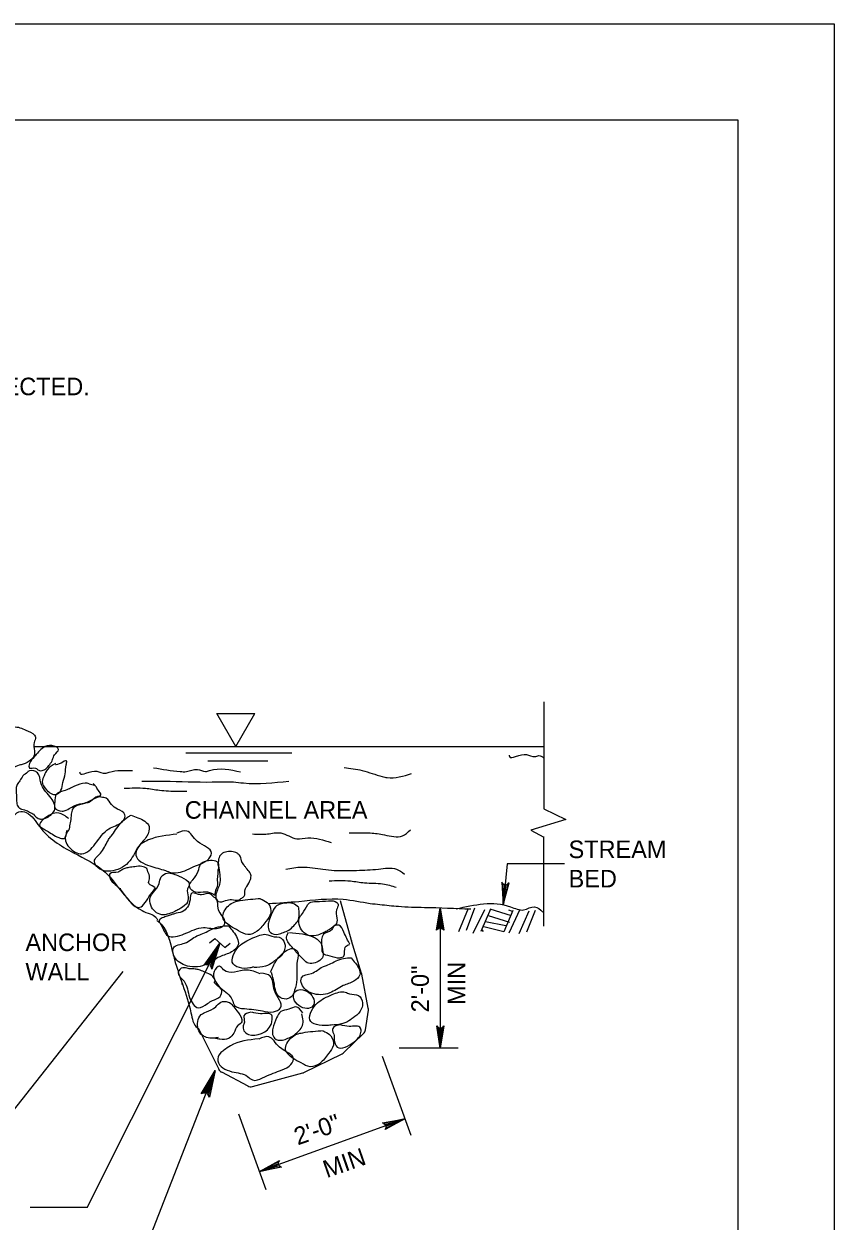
# Model space of a CAD drawing. Extents: x 5 to 910, y -47 to 547.
# Drawn here: x 719.1 to 845.7, y 360.5 to 547.5 of the extents above; entities that cross this region are included whole.
import ezdxf

# ---------------------------------------------------------------- set-up
doc = ezdxf.new("R2010")
doc.units = 0
for name, color, linetype in [('1', 7, 'Continuous'), ('2', 7, 'Continuous'), ('3', 7, 'Continuous'), ('PLT-BNDY', 7, 'Continuous')]:
    doc.layers.add(name, color=color, linetype=linetype)

msp = doc.modelspace()

# ---------------------------------------------------------------- linework, layer by layer
at = {"layer": '1'}
for p, q in [((789.55, 409.4), (788.23, 405.9)), ((788.54, 409.36), (787.03, 405.68)), ((791.09, 409.11), (789.25, 405.42)), ((792.05, 409.22), (790.54, 405.77)), ((795.04, 407.14), (791.72, 408.21)), ((795.32, 408.21), (792, 409.24)), ((795.51, 409.02), (794.11, 405.7)), ((796.61, 409.2), (794.91, 405.51)), ((795.46, 408.88), (794.91, 409.06)), ((798.01, 408.9), (796.47, 405.4)), ((799.03, 409.04), (797.65, 405.63)), ((790.95, 405.74), (790.73, 406)), ((794.11, 405.7), (790.76, 406.52)), ((794.44, 406.66), (791.25, 407.28))]:
    msp.add_line(p, q, dxfattribs=at)
msp.add_lwpolyline([(830.72, -31.53), (830.72, 532.47), (44.72, 532.47), (44.72, -31.53), (830.72, -31.53), (830.72, -5.17), (630.72, -5.17), (630.72, 59.51), (830.72, 59.51), (830.72, 88.47), (630.72, 88.47), (630.72, -31.53), (709.52, -31.53), (709.52, -5.17), (709.52, -31.53), (786.52, -31.53), (786.52, -5.17), (786.52, -17.48), (830.72, -17.48)], dxfattribs=at)
at = {"layer": '2'}
for p, q in [((800.34, 441.62), (800.34, 424.89)), ((749.26, 439.81), (755.19, 439.81)), ((752.21, 434.66), (749.26, 439.81)), ((752.21, 434.66), (755.19, 439.81)), ((720.8, 434.66), (800.34, 434.66)), ((744.39, 433.63), (760.98, 433.63)), ((747.84, 432.4), (757.22, 432.4)), ((800.32, 420.61), (800.3, 406.59)), ((794.65, 416.34), (794.03, 409.91)), ((803.59, 416.34), (794.65, 416.34)), ((784.17, 409.44), (784.17, 387.58)), ((734.57, 399.52), (716.43, 376.57)), ((786.98, 387.51), (777.76, 387.51)), ((775.1, 386.28), (779.59, 373.94)), ((752.65, 377.26), (756.93, 365.46)), ((778.66, 376.52), (755.92, 368.27)), ((729.02, 362.65), (720.07, 362.65))]:
    msp.add_line(p, q, dxfattribs=at)
for points in [[(800.34, 424.89), (803.82, 423.25), (798.33, 421.55), (800.34, 420.48)], [(793.94, 413.25), (794.17, 413.11), (794.03, 409.91), (793.94, 413.25), (793.8, 413.43), (794.03, 409.91), (794.49, 413.06), (794.74, 413.18), (794.03, 409.91), (794.92, 413.34), (794.74, 413.18)], [(783.76, 406.12), (783.99, 406.23), (784.17, 409.44), (783.76, 406.12), (783.6, 405.94), (784.17, 409.44), (784.33, 406.23), (784.56, 406.12), (784.17, 409.44), (784.72, 405.94), (784.56, 406.12)], [(747.53, 400.58), (747.85, 400.56), (749.74, 403.93), (747.53, 400.58), (747.28, 400.47), (749.74, 403.93), (748.22, 400.39), (748.42, 400.15), (749.74, 403.93), (748.48, 399.87), (748.42, 400.15)], [(784.58, 390.83), (784.35, 390.71), (784.17, 387.51), (784.58, 390.83), (784.74, 391.01), (784.17, 387.51), (784.01, 390.71), (783.78, 390.83), (784.17, 387.51), (783.62, 391.01), (783.78, 390.83)], [(747.07, 380.51), (747.39, 380.55), (748.98, 384.03), (747.07, 380.51), (746.82, 380.38), (748.98, 384.03), (747.76, 380.39), (747.98, 380.14), (748.98, 384.03), (748.09, 379.88), (747.98, 380.14)], [(775.38, 375.78), (775.59, 375.6), (778.66, 376.52), (775.38, 375.78), (775.16, 375.88), (778.66, 376.52), (775.68, 375.28), (775.66, 375.05), (778.66, 376.52), (775.57, 374.82), (775.66, 375.05)], [(759.19, 369), (759.01, 369.18), (755.92, 368.27), (759.19, 369), (759.39, 368.93), (755.92, 368.27), (758.89, 369.5), (758.91, 369.78), (755.92, 368.27), (759.03, 369.98), (758.91, 369.78)]]:
    msp.add_lwpolyline(points, dxfattribs=at)
for points in [[(794.97, 433.31), (794.99, 433.06), (795.95, 433.06), (797.67, 433.38), (798.95, 433.06), (799.59, 433.22), (800.32, 432.88)], [(727.82, 430.7), (727.85, 430.45), (728.81, 430.45), (730.52, 430.77), (731.81, 430.45), (732.45, 430.61), (736.06, 430.87)], [(739.36, 431.33), (743.54, 430.73), (744.5, 430.73), (746.22, 431.06), (747.5, 430.73), (748.14, 430.89), (752.98, 430.67)], [(769.14, 431.37), (771.98, 430.89), (775.11, 429.95), (775.89, 429.79), (779.67, 430.41)], [(734.8, 428.12), (738.09, 428.12), (740.29, 427.82), (743.13, 427.66), (744.55, 427.64)], [(737.55, 429.24), (741, 429.24), (748.55, 429.1), (751.85, 429.1), (753.43, 428.94), (760.5, 429.24)], [(754.84, 420.98), (757.2, 420.98), (759.26, 421.14), (761.75, 420.23), (763.49, 420.36), (767.13, 419.63)], [(769.94, 421.14), (773.24, 421.14), (775.44, 420.84), (778.27, 420.68), (779.53, 421.62)], [(760.04, 415.49), (762.55, 415.81), (765.85, 415.49), (767.62, 415.3), (771.11, 415.3), (774.5, 415.49), (777.33, 415.49), (778.59, 414.71)], [(766.84, 413.65), (770.14, 413.65), (772.33, 413.35), (775.17, 413.19), (777.31, 412.65)], [(762.04, 409.55), (761.16, 410.11), (759.84, 410.15), (758.61, 409.78), (757.95, 408.78), (757.33, 407.11), (757.28, 406.44), (757.63, 405.6), (758.84, 405.32), (759.68, 405.6), (760.51, 405.98), (761.29, 406.65), (761.9, 407.38), (762.05, 409.52)], [(757.36, 410.11), (762.07, 410.46), (769.01, 410.78), (773.24, 410.14), (776.21, 409.82), (777.63, 409.68), (781.7, 409.52), (788.93, 409.28)], [(786.68, 409.28), (795.15, 409.61), (797.21, 409.13), (798.91, 409.61), (800.21, 408.79)], [(757.63, 399.39), (758.54, 401.18), (760.14, 402.78), (761.15, 403.07), (761.81, 402.73), (761.81, 401.13), (761.77, 398.27), (761.42, 396.6), (761.08, 395.78), (760.1, 395.2), (758.91, 395.66), (758.2, 397.81), (757.81, 399.34)], [(754.55, 393.14), (753.49, 392.59), (753.56, 391.58), (753.38, 391.03), (753.49, 390.25), (754.2, 389.68), (757.73, 391.21), (757.89, 391.97), (757.84, 392.66), (756.07, 392.91), (754.73, 393.14)], [(762.7, 393.03), (761.6, 393.96), (760.5, 393.62), (759.27, 393.25), (758.61, 392.25), (757.99, 390.58), (757.94, 389.91), (758.29, 389.07), (759.5, 388.79), (760.34, 389.07), (761.17, 389.46), (761.95, 390.12), (762.56, 390.85), (762.56, 392.91)], [(768.66, 391.16), (767.38, 390.6), (767.37, 390.12), (767.54, 389.71), (767.61, 388.85), (768.09, 387.7), (770.71, 388.53), (771.77, 389.99), (771.72, 390.67), (769.96, 390.93), (768.61, 391.15)]]:
    msp.add_spline(points, degree=3, dxfattribs=at)
at = {"layer": '3'}
for p, q in [((729.33, 428.83), (730.16, 428.62)), ((734.14, 412.54), (734.12, 412.38)), ((770.32, 404.33), (768.6, 410.53)), ((729.02, 362.65), (749.74, 403.93)), ((771.89, 399.21), (770.33, 404.31)), ((772.93, 393.77), (771.92, 399.11)), ((743.84, 397.62), (743.73, 397.46)), ((772.49, 390.38), (772.94, 393.44)), ((746.38, 390.6), (749.55, 384.24)), ((769.11, 386.84), (772.19, 389.8)), ((762.87, 383.73), (768.86, 386.66)), ((735.14, 348.64), (748.69, 383.3)), ((749.98, 383.81), (754.11, 381.63)), ((754.83, 381.55), (762.69, 383.67))]:
    msp.add_line(p, q, dxfattribs=at)
msp.add_lwpolyline([(748.12, 403.98), (748.93, 404.64), (750.53, 403.25), (751.32, 403.95)], dxfattribs=at)
for centre, start, end in [((771.28, 404.6), 195.4612, 197.1027), ((770.94, 398.92), 10.7843, 17.1027), ((771.95, 393.59), 351.573, 10.7843), ((771.5, 390.52), 313.8767, 351.573), ((768.42, 387.56), 296.0754, 313.8767), ((750.44, 384.69), 206.5229, 242.1759), ((762.43, 384.63), 285.1011, 296.0754), ((754.57, 382.51), 242.1759, 285.1011)]:
    msp.add_arc(centre, 1, start, end, dxfattribs=at)
msp.add_ellipse((762.85, 395.2), major_axis=(-1.43, 1.06), ratio=0.71898, dxfattribs=at)
for points in [[(693.23, 441.25), (696, 438.96), (698.93, 437.45), (700.46, 437.32), (703.39, 434.02), (703.92, 432.74), (703, 430.82), (701.13, 426.08), (700.97, 424.69), (701.74, 423.54), (704.92, 421.64), (710.67, 417.8), (714.12, 418.3), (716.29, 421.64), (717.19, 423.29), (718.33, 424.44), (719.47, 424.32), (721.53, 422.15), (726.86, 418.05), (731.83, 414.99), (734.51, 411.81), (737.57, 409.02), (738.83, 408.49), (739.72, 407.99), (740, 407.55)], [(718.76, 431.78), (718.6, 431.76), (716.66, 431.21), (714.94, 432.65), (714.88, 433.86), (715.36, 434.69), (716.25, 436.08), (716.59, 437.11), (717.55, 437.68), (719.41, 437.2), (720.78, 436.4), (720.94, 436.08), (720.71, 435.26), (720.78, 433.95), (720.55, 432.92), (720.46, 432.81), (719.31, 432.01), (718.65, 431.78)], [(722.56, 431.14), (723.59, 432.6), (723.91, 433.34), (724.53, 434.18), (723.48, 434.8), (722.15, 434.48), (720.71, 433.01), (719.98, 431.99), (719.98, 431.28), (720.92, 431.28), (721.42, 430.93), (722.58, 431.14)], [(724.05, 431.96), (722.78, 431.07), (722.27, 430.08), (721.98, 429.17), (722.65, 427.89), (724.14, 427.16), (724.9, 427.8), (725.19, 429.01), (725.56, 430.38), (725.72, 431.78), (725.81, 432.35), (724.14, 431.78), (724.05, 431.78)], [(720.62, 424.05), (721.35, 423.41), (721.85, 423.31), (722.72, 423.54), (723.94, 424.87), (723.18, 426.81), (721.76, 428.94), (721.21, 430.54), (720.96, 430.71), (719.75, 430.71), (719.68, 430.64), (718.95, 430.04), (718.46, 429.27), (718.05, 428.72), (717.9, 428.06), (717.9, 427.59), (717.94, 427.11), (717.99, 425.85), (718.24, 425.17), (718.76, 424.87), (719.66, 424.57), (720, 424.39), (720.71, 424.07)], [(729.33, 428.83), (728.67, 428.92), (727.02, 428.44), (725.35, 427.71), (724.16, 427.16), (723.94, 426.01), (723.94, 425.08), (725.08, 424.55), (725.72, 424.71), (727.55, 425.6), (728.81, 425.88), (730.5, 426.7), (731.12, 427.07), (730.75, 427.78), (730.32, 428.46), (729.95, 428.85)], [(726.09, 421.6), (725.58, 420.52), (725.63, 419.91), (726.18, 418.92), (728.17, 417.87), (730.25, 419.43), (732.4, 421.78), (734.44, 422.86), (734.89, 423.57), (734.89, 423.98), (733.75, 424.87), (732.81, 425.56), (731.99, 426.56), (731.21, 426.72), (730.62, 426.84), (729.52, 426.04), (728.95, 425.83), (727.44, 425.4), (726.73, 424.87), (726.52, 424.09), (726.38, 422.97), (726.29, 422.49), (726.15, 421.55)], [(726.11, 423.38), (724.55, 424.23), (722.08, 423.18), (721.56, 422.38), (722.61, 421.53), (724.55, 420.41), (725.4, 420.29), (725.81, 421.53)], [(735.86, 423.91), (736.93, 423.52), (738.67, 422.15), (738.33, 420.66), (737.07, 419.1), (735.67, 416.79), (733, 415.24), (730.71, 415.67), (730.14, 416.66), (731.23, 418.17), (732.35, 420.11), (732.77, 420.66), (733.45, 421.6), (734.3, 422.72), (735.31, 423.61), (735.88, 423.93)], [(742.99, 420.94), (738.55, 420.04), (737.59, 419.52), (736.93, 418.83), (736.61, 417.69), (738.78, 415.99), (741.23, 415.26), (742.07, 414.98), (743.57, 415.01), (746.24, 416.13), (747.75, 416.86), (748.42, 417.96), (746.24, 419.81), (744.55, 421.44), (742.99, 421.1)], [(748.9, 411.41), (748.49, 411.68), (747.14, 411.88), (745.59, 412.01), (745.01, 412.97), (745.49, 413.8), (746.36, 415.17), (746.7, 416.22), (747.66, 416.79), (749.41, 416.37), (749.4, 416.21), (749.51, 415.91), (749.46, 415.5), (749.4, 414.72), (749.33, 413.69), (749.33, 412.85), (749.14, 412.39), (748.9, 411.38)], [(753.11, 416.77), (752.79, 417.69), (752.42, 417.98), (751.57, 418.24), (749.83, 417.69), (749.56, 415.67), (749.67, 413.09), (749.1, 411.33), (749.24, 410.69), (749.49, 410.46), (750.63, 410.57), (751.57, 410.75), (752.63, 410.66), (753.15, 410.98), (753.52, 411.26), (753.7, 412.33), (753.93, 412.79), (754.5, 413.87), (754.59, 414.6), (754.32, 415.1), (753.72, 415.83), (753.49, 416.18), (753.04, 416.75)], [(738.35, 415.58), (737.53, 415.92), (736.45, 415.86), (735.53, 415.74), (734.89, 415.58), (734.35, 415.31), (733.82, 415.03), (732.56, 414.78), (732.72, 413.77), (733.64, 412.86), (737.43, 409.59), (738.26, 410.53), (739.15, 411.85), (739.61, 412.58), (738.62, 413.23), (738.72, 413.96), (738.72, 414.41), (738.42, 415.31), (738.34, 415.59)], [(742.72, 408.89), (741.77, 408.51), (740.64, 408.37), (738.94, 409.84), (738.85, 411.07), (739.36, 411.88), (740.23, 413.25), (740.57, 414.28), (741.51, 414.87), (743.38, 414.37), (744.76, 413.57), (744.94, 413.25), (744.69, 412.42), (744.76, 411.14), (744.53, 410.09), (744.46, 410.02), (743.31, 409.2), (742.71, 408.89)], [(741.53, 408.16), (740.74, 407.86), (740.23, 407.44), (740.43, 406.98), (741.6, 405.08), (744.18, 405.38), (747.18, 406.36), (749.49, 406.25), (750.25, 406.61), (750.5, 407), (749.95, 408.4), (749.45, 409.4), (749.26, 410.69), (748.64, 411.26), (748.16, 411.65), (746.86, 411.49), (746.24, 411.6), (745.33, 411.75), (745.07, 410.71), (743.84, 408.84), (742.62, 408.52), (742.11, 408.34), (741.47, 408.14)], [(756.03, 410.85), (756.33, 410.73), (757.32, 410.07), (757.68, 408.6), (756.93, 407.32), (755.55, 405.79), (754.09, 405.26), (752.65, 405.86), (751.39, 406.57), (750.61, 407.23), (750.22, 407.94), (750.43, 408.9), (751.98, 410.34), (752.9, 410.57), (756.1, 410.91)], [(765.99, 405.58), (765.04, 405.2), (763.91, 405.07), (762.21, 406.53), (762.12, 407.77), (762.63, 408.57), (763.5, 409.94), (763.73, 410.21), (764.79, 410.44), (766.73, 410.53), (768.03, 410.26), (768.21, 409.94), (767.96, 409.12), (768.03, 407.84), (767.8, 406.78), (767.73, 406.72), (766.58, 405.89), (765.98, 405.58)], [(739.86, 407.46), (740.02, 407.35), (742.42, 402.2), (743.95, 397.35), (745.21, 393.07), (746.24, 390.69), (746.38, 390.6)], [(751.09, 406.61), (751.82, 405.72), (752.6, 403.68), (751.55, 402.56), (749.72, 401.81), (747.39, 400.53), (744.27, 400.48), (742.51, 402.06), (742.47, 403.18), (744.23, 403.94), (746.15, 405.06), (746.79, 405.31), (747.84, 405.79), (749.12, 406.36), (750.47, 406.61), (751.09, 406.64)], [(770.06, 403.75), (769.12, 405.64), (768.3, 406.74), (767.5, 406.51), (767.16, 405.95), (765.93, 405.32), (765.73, 404.91), (765.6, 404.13), (765.67, 403.01), (765.76, 402.46), (766.9, 401.96), (768.46, 401.64), (769.1, 401.92), (769.33, 403.31), (770.01, 403.72)], [(754.98, 400.24), (754.43, 400.06), (751.68, 400.97), (751.96, 402.35), (752.9, 403.6), (755.19, 404.88), (757.24, 405.25), (757.88, 405), (759.3, 404.72), (759.92, 403.6), (759.3, 401.96), (758.16, 401.04), (758.04, 400.95), (756.86, 400.35), (755.05, 400.13)], [(760.59, 405.58), (762.67, 405.37), (765.44, 404.02), (765.85, 402.56), (765.76, 401.64), (765.35, 401.23), (763.38, 400.88), (762.67, 401.53), (761.62, 402.56), (761.3, 402.97), (760.27, 404.34), (760.18, 405.05), (760.47, 405.58)], [(748.99, 398.19), (748.46, 398.88), (747.48, 399.36), (746.65, 399.7), (746.01, 399.86), (745.37, 399.91), (744.78, 399.96), (743.94, 400.09), (743.22, 399.41), (744.14, 397.97), (745, 395.46), (746.36, 393.85), (747.8, 394.51), (748.58, 394.95), (749.77, 395.61), (750.03, 396.55), (749.64, 397.07), (748.92, 397.9), (749.15, 398.06)], [(756.02, 399.12), (753.93, 399.72), (750.32, 399.78), (749.68, 400.33), (748.86, 399.51), (749.91, 396.92), (751.65, 395.09), (752.04, 394.2), (753.57, 393.7), (756.41, 393.35), (758.1, 393.19), (759.22, 393.83), (758.26, 396.53), (757.6, 398.78), (756.09, 399.26)], [(770.25, 401.62), (770.91, 400.82), (771.61, 398.99), (770.66, 397.98), (769.01, 397.3), (766.91, 396.15), (764.11, 396.11), (762.53, 397.53), (762.49, 398.54), (764.07, 399.21), (765.8, 400.22), (766.38, 400.45), (767.33, 400.88), (768.48, 401.4), (769.69, 401.62), (770.25, 401.64)], [(767.26, 391.15), (766.53, 391.07), (763.78, 391.98), (764.06, 393.35), (765, 394.61), (767.28, 395.89), (769.34, 396.26), (769.98, 396.01), (771.4, 395.73), (772.02, 394.61), (771.4, 392.96), (770.26, 392.05), (770.14, 391.96), (768.95, 391.36), (767.15, 391.13)], [(749.48, 389.18), (748.97, 389.11), (746.98, 389.54), (746.27, 391.69), (746.82, 392.77), (747.62, 393.2), (749.09, 393.98), (749.89, 394.71), (751.01, 394.74), (752.38, 393.36), (753.16, 391.99), (753.16, 391.65), (752.54, 391.05), (751.92, 389.89), (751.19, 389.11), (751.1, 389.06), (749.73, 388.92), (749.04, 389.06)], [(755.78, 388.98), (751.38, 387.91), (750.35, 387.2), (749.76, 386.7), (749.44, 385.55), (751.61, 383.86), (754.06, 383.13), (754.84, 382.56), (756.39, 382.88), (759.07, 384), (760.58, 384.73), (761.24, 385.83), (759.07, 387.68), (757.38, 389.31), (755.82, 388.96)], [(765.82, 390.22), (766.12, 390.1), (767.1, 389.44), (767.47, 387.98), (766.71, 386.69), (765.34, 385.16), (763.87, 384.64), (762.43, 385.23), (761.17, 385.94), (760.4, 386.6), (760.01, 387.31), (760.21, 388.27), (761.77, 389.71), (762.68, 389.94), (765.89, 390.29)]]:
    msp.add_spline(points, degree=3, dxfattribs=at)
at = {"layer": 'PLT-BNDY'}
msp.add_lwpolyline([(4.72, 547.47), (845.72, 547.47), (845.72, -46.53), (4.72, -46.53)], close=True, dxfattribs=at)

# ---------------------------------------------------------------- texts
at = {"layer": '3'}
for s, height, p in [('ON THE DRAWINGS, OR AS DIRECTED.', 2.7454, (660.05, 489.49)), ('CHANNEL AREA', 2.7454, (744.25, 423.36)), ('STREAM', 2.745, (804.23, 417.21)), ('BED', 2.745, (804.23, 412.63)), ('ANCHOR', 2.745, (719.35, 402.69)), ('WALL', 2.745, (719.35, 398.11))]:
    msp.add_text(s, height=height, dxfattribs=at).set_placement(p)
for s, rotation, p in [('2\'-0"', 90, (782.4, 393.12)), (' MIN', 90, (788.09, 393.27)), ('2\'-0"', 19.2468, (761.91, 372.34)), ('MIN', 19.2468, (766.44, 367.22))]:
    msp.add_text(s, height=2.745, rotation=rotation, dxfattribs=at).set_placement(p)

doc.saveas('drawing.dxf')
